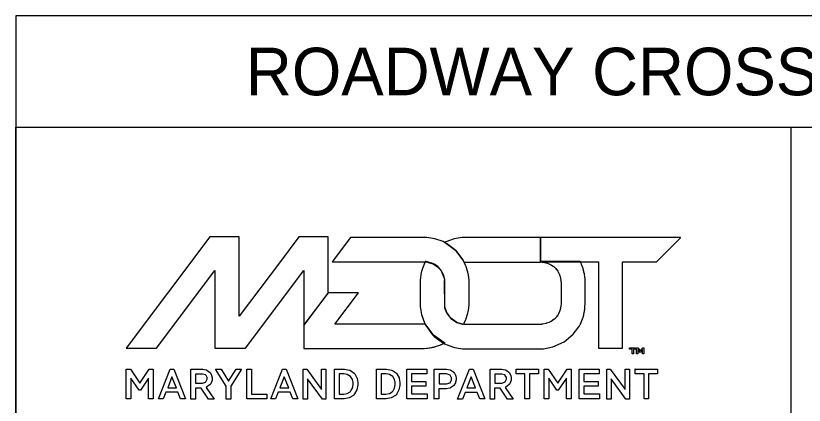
# Model space of a CAD drawing. Extents: x 0 to 34, y 0 to 29.3.
# Drawn here: x 22.041 to 24.694, y 1.676 to 2.986 of the extents above; entities that cross this region are included whole.
import ezdxf

# ---------------------------------------------------------------- set-up
doc = ezdxf.new("R2010")
doc.units = 0
for name, color, linetype in [('G-BORD-LINE', 7, 'Continuous'), ('G-MSHA-LOGO', 7, 'Continuous'), ('G-TTLB-TEXT', 7, 'Continuous'), ('G-USER-LINE', 7, 'Continuous')]:
    doc.layers.add(name, color=color, linetype=linetype)

msp = doc.modelspace()

# ---------------------------------------------------------------- linework, layer by layer
at = {"layer": 'G-BORD-LINE'}
for p, q in [((27.4368, 2.9861), (22.0409, 2.9861)), ((22.0411, 2.9861), (22.0411, 0.75)), ((22.0411, 2.6111), (27.4368, 2.6111))]:
    msp.add_line(p, q, dxfattribs=at)
at = {"layer": 'G-MSHA-LOGO'}
for points in [[(23.0107, 1.9446), (23.0926, 2.0534), (23.0926, 2.2421), (22.9931, 2.2421), (22.9314, 2.1597), (22.793, 1.9757), (22.793, 2.2421), (22.6936, 2.2421), (22.4121, 1.8679), (22.5148, 1.8679), (22.7112, 2.1291), (22.7112, 1.8679), (22.8143, 1.8679), (23.0107, 2.1291)], [(23.4186, 2.1581), (23.421, 2.158), (23.444, 2.1519), (23.446, 2.1508), (23.4486, 2.1496), (23.4601, 2.1413), (23.4697, 2.1313), (23.4714, 2.1291), (23.4732, 2.1265), (23.48, 2.1124), (23.4836, 2.0971), (23.4839, 2.0938), (23.4839, 2.0938), (23.4839, 2.0933), (23.4839, 2.0933), (23.4839, 2.0925), (23.4839, 2.0908), (23.4839, 2.0902), (23.4839, 2.0192), (23.4839, 2.0185), (23.4839, 2.0167), (23.4839, 2.0161), (23.4839, 2.0161), (23.4839, 2.0156), (23.4839, 2.0156), (23.4839, 2.014), (23.4833, 2.0105), (23.4833, 2.0094), (23.4842, 2.0035), (23.4908, 1.9865), (23.5051, 1.9678), (23.5254, 1.9543), (23.5439, 1.9486), (23.5479, 1.9483), (23.5487, 1.9495), (23.5492, 1.9503), (23.5492, 1.9503), (23.5498, 1.9516), (23.5559, 1.9649), (23.5564, 1.9663), (23.5569, 1.9678), (23.5612, 1.9819), (23.5616, 1.9834), (23.5617, 1.9842), (23.5635, 1.9915), (23.5637, 1.9922), (23.564, 1.9945), (23.5663, 2.0134), (23.5663, 2.0197), (23.5663, 2.0892), (23.5663, 2.0961), (23.564, 2.1144), (23.5637, 2.1166), (23.5635, 2.1174), (23.5619, 2.1247), (23.5616, 2.1255), (23.5612, 2.1269), (23.5569, 2.1411), (23.5564, 2.1425), (23.5559, 2.144), (23.5498, 2.1573), (23.5492, 2.1586), (23.5455, 2.1656), (23.5216, 2.1963), (23.4909, 2.2203), (23.4839, 2.2239), (23.4787, 2.2266), (23.4509, 2.2363), (23.4239, 2.2405), (23.4149, 2.2405), (23.1678, 2.2405), (23.1061, 2.1586), (23.4149, 2.1586), (23.4152, 2.1585), (23.4177, 2.1581)], [(23.5497, 2.1576), (23.551, 2.1576), (23.5517, 2.1576), (23.8052, 2.1576), (23.8055, 2.1576), (23.8064, 2.1576), (23.8067, 2.1576), (23.8072, 2.1586), (23.8072, 2.24), (23.8071, 2.24), (23.8056, 2.24), (23.8052, 2.24), (23.5517, 2.24), (23.5427, 2.24), (23.5157, 2.2356), (23.488, 2.226), (23.4839, 2.2239), (23.4909, 2.2203), (23.5216, 2.1963), (23.5455, 2.1656), (23.5492, 2.1586)], [(23.8072, 2.24), (23.8072, 2.1581), (24.0016, 2.1581), (24.0016, 1.8679), (24.083, 1.8679), (24.083, 2.1581), (24.1965, 2.1581), (24.2778, 2.2395), (24.2778, 2.24)], [(23.4854, 1.8845), (23.4851, 1.8845), (23.4845, 1.8849), (23.4844, 1.885), (23.4809, 1.8868), (23.4498, 1.9096), (23.4471, 1.9125), (23.4443, 1.9152), (23.4219, 1.9459), (23.4201, 1.9492), (23.4197, 1.9492), (23.4188, 1.9492), (23.4186, 1.9492), (23.4176, 1.9492), (23.4156, 1.9492), (23.4149, 1.9492), (23.1149, 1.9492), (23.1947, 2.0544), (23.0921, 2.0544), (23.0102, 1.9461), (23.0102, 1.8674), (23.4144, 1.8674), (23.4167, 1.8674), (23.423, 1.8678), (23.4237, 1.8679), (23.4259, 1.8679), (23.4318, 1.8688), (23.4326, 1.8689), (23.4332, 1.8689), (23.4347, 1.8694), (23.4352, 1.8694), (23.4357, 1.8696), (23.4403, 1.8704), (23.4409, 1.8705), (23.4416, 1.8705), (23.4434, 1.871), (23.444, 1.871), (23.4443, 1.8711), (23.4487, 1.8719), (23.4491, 1.872), (23.4494, 1.8722), (23.452, 1.8729), (23.4522, 1.873), (23.4526, 1.8732), (23.4565, 1.8745), (23.4569, 1.8746), (23.4572, 1.8747), (23.4597, 1.8755), (23.46, 1.8756), (23.4604, 1.8758), (23.4643, 1.8771), (23.4647, 1.8772), (23.4649, 1.8773), (23.4675, 1.8781), (23.4678, 1.8782), (23.4682, 1.8784), (23.4726, 1.8802), (23.473, 1.8803), (23.4732, 1.8804), (23.4753, 1.8812), (23.4756, 1.8814), (23.4762, 1.8816), (23.4823, 1.8846), (23.4828, 1.885), (23.4832, 1.8847), (23.4848, 1.8845)], [(24.1067, 1.8688), (24.1269, 1.8688), (24.1269, 1.8652), (24.1192, 1.8652), (24.1192, 1.8486), (24.115, 1.8486), (24.115, 1.8652), (24.1067, 1.8652)], [(24.13, 1.8688), (24.1337, 1.8688), (24.1425, 1.8589), (24.1508, 1.8688), (24.1544, 1.8688), (24.1544, 1.8486), (24.1497, 1.8486), (24.1497, 1.8631), (24.142, 1.8538), (24.1342, 1.8631), (24.1342, 1.8486), (24.13, 1.8486)], [(22.4127, 1.7974), (22.4267, 1.7974), (22.4588, 1.7508), (22.4899, 1.7974), (22.5033, 1.7974), (22.5033, 1.6974), (22.4878, 1.6974), (22.4878, 1.7668), (22.4603, 1.7269), (22.4562, 1.7269), (22.4282, 1.7668), (22.4282, 1.6974), (22.4127, 1.6974)], [(22.5609, 1.7974), (22.5728, 1.7974), (22.6122, 1.6974), (22.5956, 1.6974), (22.5868, 1.7197), (22.5459, 1.7197), (22.537, 1.6974), (22.521, 1.6974)], [(22.6303, 1.6968), (22.6303, 1.7969), (22.6656, 1.7969), (22.67, 1.7969), (22.6819, 1.7947), (22.6832, 1.7943), (22.6844, 1.7939), (22.6934, 1.7878), (22.6941, 1.787), (22.6947, 1.7863), (22.6994, 1.7781), (22.6998, 1.7772), (22.7, 1.7763), (22.7013, 1.768), (22.7013, 1.7653), (22.7013, 1.7607), (22.697, 1.7484), (22.6961, 1.7471), (22.6952, 1.7458), (22.6832, 1.7368), (22.6816, 1.7363), (22.7086, 1.6963), (22.6894, 1.6963), (22.6651, 1.7331), (22.6459, 1.7331), (22.6459, 1.6963), (22.6303, 1.6963)], [(22.6459, 1.7808), (22.6459, 1.7502), (22.6661, 1.7502), (22.6696, 1.7502), (22.6791, 1.7538), (22.6801, 1.7544), (22.6808, 1.755), (22.6852, 1.7635), (22.6852, 1.7663), (22.6852, 1.769), (22.6814, 1.7765), (22.6806, 1.7772), (22.6798, 1.7778), (22.6691, 1.7808), (22.6656, 1.7808)], [(22.7645, 1.7404), (22.7645, 1.6968), (22.749, 1.6968), (22.749, 1.7404), (22.7127, 1.7974), (22.7319, 1.7974), (22.7568, 1.7575), (22.7822, 1.7974), (22.8008, 1.7974)], [(22.8185, 1.7974), (22.834, 1.7974), (22.834, 1.7135), (22.8853, 1.7135), (22.8853, 1.6974), (22.8185, 1.6974)], [(22.9387, 1.7974), (22.9506, 1.7974), (22.99, 1.6974), (22.9734, 1.6974), (22.9646, 1.7197), (22.9236, 1.7197), (22.9148, 1.6974), (22.8993, 1.6974)], [(23.0729, 1.6968), (23.0232, 1.7653), (23.0232, 1.6968), (23.0081, 1.6968), (23.0081, 1.7969), (23.0201, 1.7969), (23.0698, 1.7285), (23.0698, 1.7969), (23.0848, 1.7969), (23.0848, 1.6968)], [(23.1133, 1.7974), (23.1413, 1.7974), (23.1473, 1.7974), (23.1635, 1.7944), (23.1652, 1.7938), (23.1668, 1.7931), (23.1802, 1.7841), (23.1812, 1.7829), (23.1821, 1.7817), (23.1891, 1.7688), (23.1895, 1.7673), (23.1899, 1.7659), (23.1921, 1.753), (23.1921, 1.7487), (23.1921, 1.7435), (23.1889, 1.7281), (23.1813, 1.7139), (23.1791, 1.7114), (23.1769, 1.709), (23.1628, 1.7009), (23.1455, 1.6974), (23.1398, 1.6974), (23.1133, 1.6974)], [(23.1289, 1.7808), (23.1289, 1.7135), (23.1408, 1.7135), (23.1447, 1.7135), (23.1563, 1.7158), (23.1658, 1.7212), (23.1672, 1.7228), (23.1686, 1.7243), (23.1738, 1.734), (23.176, 1.745), (23.176, 1.7487), (23.176, 1.7523), (23.1739, 1.763), (23.1674, 1.7732), (23.1565, 1.7793), (23.1451, 1.7813), (23.1413, 1.7813), (23.1289, 1.7813)], [(23.2548, 1.7974), (23.2828, 1.7974), (23.2887, 1.7974), (23.3049, 1.7944), (23.3066, 1.7938), (23.3083, 1.7931), (23.3216, 1.7841), (23.3227, 1.7829), (23.3236, 1.7817), (23.3306, 1.7688), (23.331, 1.7673), (23.3314, 1.7659), (23.3336, 1.753), (23.3336, 1.7487), (23.3336, 1.7435), (23.3304, 1.7281), (23.3228, 1.7139), (23.3206, 1.7114), (23.3184, 1.709), (23.3042, 1.7009), (23.287, 1.6974), (23.2812, 1.6974), (23.2548, 1.6974)], [(23.2709, 1.7808), (23.2709, 1.7135), (23.2828, 1.7135), (23.2867, 1.7135), (23.2983, 1.7158), (23.3078, 1.7212), (23.3092, 1.7228), (23.3106, 1.7243), (23.3157, 1.734), (23.318, 1.745), (23.318, 1.7487), (23.318, 1.7523), (23.3159, 1.763), (23.3094, 1.7732), (23.2985, 1.7793), (23.2871, 1.7813), (23.2833, 1.7813), (23.2709, 1.7813)], [(23.3569, 1.7974), (23.4237, 1.7974), (23.4237, 1.7813), (23.3725, 1.7813), (23.3725, 1.7559), (23.4206, 1.7559), (23.4206, 1.7404), (23.3725, 1.7404), (23.3725, 1.714), (23.4253, 1.714), (23.4253, 1.6979), (23.3569, 1.6979)], [(23.4491, 1.6968), (23.4491, 1.7969), (23.4854, 1.7969), (23.4901, 1.7969), (23.5028, 1.7947), (23.5041, 1.7943), (23.5054, 1.7938), (23.5148, 1.7873), (23.5155, 1.7865), (23.5161, 1.7858), (23.5209, 1.7771), (23.5212, 1.7761), (23.5214, 1.7753), (23.5227, 1.767), (23.5227, 1.7642), (23.5227, 1.7613), (23.521, 1.7532), (23.5207, 1.7523), (23.5203, 1.7514), (23.5151, 1.7427), (23.5144, 1.742), (23.5138, 1.7412), (23.5038, 1.7347), (23.5025, 1.7342), (23.5012, 1.7337), (23.489, 1.7316), (23.4849, 1.7316), (23.4642, 1.7316), (23.4642, 1.6974), (23.4491, 1.6974)], [(23.4652, 1.7813), (23.4652, 1.7476), (23.4859, 1.7476), (23.49, 1.7476), (23.5023, 1.7519), (23.5077, 1.7616), (23.5077, 1.7648), (23.5077, 1.7679), (23.5026, 1.7771), (23.4909, 1.7813), (23.487, 1.7813)], [(23.5678, 1.7974), (23.5798, 1.7974), (23.6191, 1.6974), (23.6025, 1.6974), (23.5937, 1.7191), (23.5528, 1.7191), (23.544, 1.6968), (23.5279, 1.6968)], [(23.6368, 1.6968), (23.6368, 1.7969), (23.672, 1.7969), (23.6764, 1.7969), (23.6883, 1.7947), (23.6896, 1.7943), (23.6908, 1.7939), (23.6998, 1.7878), (23.7005, 1.787), (23.7011, 1.7863), (23.7058, 1.7781), (23.7062, 1.7772), (23.7064, 1.7763), (23.7077, 1.768), (23.7077, 1.7653), (23.7077, 1.7607), (23.7035, 1.7484), (23.7026, 1.7471), (23.7016, 1.7458), (23.6896, 1.7368), (23.688, 1.7363), (23.715, 1.6963), (23.6958, 1.6963), (23.6715, 1.7331), (23.6523, 1.7331), (23.6523, 1.6963), (23.6368, 1.6963)], [(23.6528, 1.7808), (23.6528, 1.7502), (23.673, 1.7502), (23.6765, 1.7502), (23.6861, 1.7538), (23.687, 1.7544), (23.6878, 1.755), (23.6922, 1.7635), (23.6922, 1.7663), (23.6922, 1.769), (23.6883, 1.7765), (23.6875, 1.7772), (23.6867, 1.7778), (23.6761, 1.7808), (23.6725, 1.7808)], [(23.7243, 1.7974), (23.8005, 1.7974), (23.8005, 1.7813), (23.7699, 1.7813), (23.7699, 1.6974), (23.7544, 1.6974), (23.7544, 1.7813), (23.7243, 1.7813)], [(23.8187, 1.7974), (23.8326, 1.7974), (23.8648, 1.7508), (23.8959, 1.7974), (23.9094, 1.7974), (23.9094, 1.6974), (23.8938, 1.6974), (23.8938, 1.7668), (23.8663, 1.7269), (23.8622, 1.7269), (23.8342, 1.7668), (23.8342, 1.6974), (23.8187, 1.6974)], [(23.9373, 1.7974), (24.0042, 1.7974), (24.0042, 1.7813), (23.9529, 1.7813), (23.9529, 1.7559), (24.0011, 1.7559), (24.0011, 1.7404), (23.9529, 1.7404), (23.9529, 1.714), (24.0057, 1.714), (24.0057, 1.6979), (23.9373, 1.6979)], [(24.0944, 1.6968), (24.0446, 1.7653), (24.0446, 1.6968), (24.0296, 1.6968), (24.0296, 1.7969), (24.0415, 1.7969), (24.0912, 1.7285), (24.0912, 1.7969), (24.1063, 1.7969), (24.1063, 1.6968)], [(24.1244, 1.7974), (24.2006, 1.7974), (24.2006, 1.7813), (24.1705, 1.7813), (24.1705, 1.6974), (24.155, 1.6974), (24.155, 1.7813), (24.1249, 1.7813), (24.1249, 1.7974)], [(22.5521, 1.7342), (22.5816, 1.7342), (22.5666, 1.772)], [(22.9299, 1.7342), (22.9594, 1.7342), (22.9444, 1.772)], [(23.5585, 1.7342), (23.588, 1.7342), (23.573, 1.772)]]:
    msp.add_lwpolyline(points, close=True, dxfattribs=at)
for points in [[(23.4839, 2.0503), (23.4839, 2.0892), (23.4839, 2.0902), (23.4839, 2.0925), (23.4839, 2.0933), (23.4839, 2.0949), (23.4844, 2.0984), (23.4844, 2.0995), (23.484, 2.1023), (23.474, 2.1274), (23.4725, 2.1296), (23.4708, 2.1319), (23.4609, 2.1423), (23.4491, 2.1506), (23.4465, 2.1519), (23.4443, 2.1531), (23.4216, 2.159), (23.4191, 2.1591), (23.4191, 2.1589), (23.4186, 2.1581), (23.4175, 2.1561), (23.4094, 2.1358), (23.4087, 2.1337), (23.4085, 2.1331), (23.4064, 2.1257), (23.4061, 2.1249), (23.4055, 2.1221), (23.402, 2.0974), (23.402, 2.0892), (23.402, 2.0503), (23.402, 2.0461)], [(23.957, 2.0892), (23.957, 2.0914), (23.9566, 2.0972), (23.9565, 2.098), (23.9565, 2.0985), (23.9565, 2.1006), (23.9565, 2.1021), (23.956, 2.1056), (23.956, 2.1068), (23.956, 2.1072), (23.956, 2.1081), (23.956, 2.1083), (23.956, 2.1086), (23.956, 2.1092), (23.956, 2.1094), (23.9559, 2.1099), (23.9551, 2.1151), (23.9549, 2.1156), (23.9549, 2.1161), (23.9544, 2.1173), (23.9544, 2.1177), (23.9543, 2.1183), (23.953, 2.1239), (23.9529, 2.1244), (23.9529, 2.1249), (23.9529, 2.1255), (23.9526, 2.1262), (23.9505, 2.134), (23.9503, 2.1348), (23.9499, 2.1361), (23.9451, 2.149), (23.9446, 2.1503), (23.9443, 2.151), (23.9412, 2.1574), (23.941, 2.1581), (23.941, 2.1584), (23.9404, 2.1591), (23.8093, 2.1591), (23.8088, 2.1581), (23.8103, 2.1581), (23.8109, 2.1581), (23.8115, 2.1581), (23.8132, 2.1577), (23.8135, 2.1576), (23.8145, 2.1575), (23.825, 2.1554), (23.8259, 2.155), (23.8268, 2.1547), (23.8354, 2.1518), (23.8363, 2.1514), (23.8368, 2.1511), (23.8414, 2.1485), (23.842, 2.1483), (23.8424, 2.1483), (23.8425, 2.1483), (23.8429, 2.148), (23.8473, 2.1454), (23.8477, 2.1451), (23.8482, 2.1448), (23.8482, 2.1446), (23.8486, 2.1444), (23.8524, 2.1414), (23.8529, 2.141), (23.8534, 2.1405), (23.8537, 2.1402), (23.8567, 2.1371), (23.857, 2.1368), (23.8574, 2.1363), (23.8575, 2.1363), (23.858, 2.1358), (23.8583, 2.1356), (23.8605, 2.133), (23.8606, 2.1327), (23.8611, 2.1322), (23.8613, 2.1321), (23.8621, 2.1308), (23.8622, 2.1306), (23.8624, 2.1304), (23.8646, 2.1273), (23.8648, 2.127), (23.8649, 2.1269), (23.8657, 2.1252), (23.8658, 2.1249), (23.8662, 2.1244), (23.8663, 2.1244), (23.8664, 2.1242), (23.8678, 2.1216), (23.8679, 2.1213), (23.868, 2.121), (23.8688, 2.119), (23.8689, 2.1187), (23.869, 2.1185), (23.8703, 2.1155), (23.8705, 2.1151), (23.8706, 2.115), (23.871, 2.113), (23.871, 2.1128), (23.8714, 2.1121), (23.8715, 2.112), (23.8716, 2.1117), (23.8726, 2.1096), (23.8726, 2.1089), (23.8727, 2.1086), (23.8734, 2.1055), (23.8736, 2.1052), (23.8736, 2.1045), (23.8741, 2.1027), (23.8741, 2.1021), (23.8742, 2.1018), (23.8746, 2.0989), (23.8746, 2.098), (23.8746, 2.0973), (23.8752, 2.0959), (23.8752, 2.0954), (23.8752, 2.0937), (23.8757, 2.0899), (23.8757, 2.0887), (23.8757, 2.0176), (23.8757, 2.016), (23.8753, 2.0114), (23.8752, 2.0109), (23.8752, 2.0103), (23.8747, 2.0086), (23.8746, 2.0083), (23.8746, 2.0073), (23.8741, 2.005), (23.8741, 2.0042), (23.8741, 2.0034), (23.8736, 2.0017), (23.8736, 2.0011), (23.8734, 2.0008), (23.8727, 1.9977), (23.8726, 1.9974), (23.8724, 1.9972), (23.8716, 1.9946), (23.8715, 1.9943), (23.8715, 1.9941), (23.8711, 1.9934), (23.871, 1.9933), (23.8705, 1.9918), (23.8705, 1.9912), (23.8703, 1.991), (23.869, 1.988), (23.8689, 1.9876), (23.8688, 1.9874), (23.868, 1.9853), (23.8679, 1.985), (23.8678, 1.9848), (23.8664, 1.9821), (23.8663, 1.9819), (23.8659, 1.9814), (23.8658, 1.9814), (23.8657, 1.9813), (23.8649, 1.9796), (23.8648, 1.9793), (23.8645, 1.979), (23.8624, 1.9759), (23.8622, 1.9757), (23.8621, 1.9756), (23.8613, 1.9742), (23.8611, 1.9741), (23.8606, 1.9736), (23.8604, 1.9734), (23.8581, 1.9708), (23.858, 1.9705), (23.8575, 1.97), (23.8571, 1.9695), (23.857, 1.9695), (23.8567, 1.9692), (23.8536, 1.9661), (23.8534, 1.9658), (23.8529, 1.9653), (23.8524, 1.9651), (23.8486, 1.962), (23.8482, 1.9617), (23.8477, 1.9613), (23.8477, 1.9611), (23.8473, 1.9609), (23.843, 1.9583), (23.8425, 1.958), (23.8421, 1.958), (23.842, 1.958), (23.8416, 1.9578), (23.8368, 1.9552), (23.8363, 1.9549), (23.8355, 1.9546), (23.8268, 1.9516), (23.8259, 1.9513), (23.8249, 1.9511), (23.8145, 1.9489), (23.8135, 1.9487), (23.8128, 1.9487), (23.8111, 1.9483), (23.8109, 1.9482), (23.81, 1.9482), (23.8079, 1.9482), (23.8072, 1.9482), (23.5538, 1.9482), (23.5529, 1.9482), (23.5509, 1.9482), (23.5502, 1.9482), (23.5439, 1.9486), (23.5254, 1.9543), (23.5051, 1.9684), (23.491, 1.9885), (23.4853, 2.0068), (23.4849, 2.013), (23.4849, 2.014), (23.4849, 2.0164), (23.4849, 2.0171), (23.4849, 2.0503), (23.4839, 2.0503)], [(23.402, 2.0461), (23.402, 2.0171), (23.402, 2.0081), (23.4064, 1.9811), (23.416, 1.9534), (23.4186, 1.9482), (23.4204, 1.9447), (23.4433, 1.9132), (23.446, 1.9104), (23.4487, 1.9077), (23.4804, 1.8847), (23.4839, 1.8829), (23.4891, 1.8802), (23.5168, 1.8705), (23.5438, 1.8663), (23.5528, 1.8663), (23.8062, 1.8663), (23.8167, 1.8663), (23.8483, 1.8723), (23.8858, 1.889), (23.917, 1.9149), (23.9358, 1.9393), (23.9404, 1.9482), (23.9408, 1.9488), (23.9438, 1.9553), (23.9441, 1.956), (23.9446, 1.9573), (23.9494, 1.9702), (23.9498, 1.9715), (23.95, 1.9723), (23.9522, 1.9801), (23.9523, 1.9809), (23.9523, 1.9814), (23.9523, 1.9819), (23.9525, 1.9824), (23.9538, 1.9881), (23.9539, 1.9886), (23.9539, 1.9892), (23.9544, 1.9903), (23.9544, 1.9907), (23.9545, 1.9912), (23.9553, 1.9964), (23.9555, 1.9969), (23.9555, 1.9972), (23.9555, 1.9978), (23.9555, 1.998), (23.9555, 1.9984), (23.9555, 1.9992), (23.9555, 1.9995), (23.9555, 2.0011), (23.956, 2.0046), (23.956, 2.0057), (23.956, 2.0078), (23.956, 2.0083), (23.956, 2.0105), (23.9565, 2.0155), (23.9565, 2.0171), (23.957, 2.0892)]]:
    msp.add_lwpolyline(points, dxfattribs=at)
at = {"layer": 'G-USER-LINE'}
msp.add_lwpolyline([(22.0411, 2.6111), (24.6494, 2.6111), (24.6494, 0.75), (22.0411, 0.75)], close=True, dxfattribs=at)

# ---------------------------------------------------------------- texts
at = {"layer": 'G-TTLB-TEXT'}
msp.add_text('ROADWAY CROSS SECTION SHEET', height=0.16, dxfattribs=at).set_placement((22.8154, 2.7186))

doc.saveas('drawing.dxf')
